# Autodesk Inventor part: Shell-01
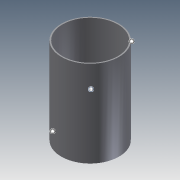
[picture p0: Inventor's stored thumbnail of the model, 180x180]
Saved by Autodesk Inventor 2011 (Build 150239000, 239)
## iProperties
Created: 2010-06
Part Number: Shell-01
Document SubType Name: Modeling
Designer: mklassen
Density: 1 g/cm^3
OD: 24.000 in
THK: 0.500 in
LEN: 3.000 ft
Author: mklassen
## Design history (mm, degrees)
sketch "skShell"
  geometry: C1 r 304.8 at (0, 0); C2 r 292.1 at (0, 0); 1 further point
  constraints: 2 centre point, 1 coincident
  dimensions: "d0" = 609.6 diameter of C1 (derived); "d1" = 12.7 radial gap between concentric circles of C2 C1 (derived)
extrude "Shell" new body sketch "skShell" stored distance "d2" = 914.4 (derived); taper "d3" = 0 deg
body "Solid1"
other parameters: "d4" = 0, "d5" = 0, "d6" = 0, "d7" = 0, "d8" = 0
